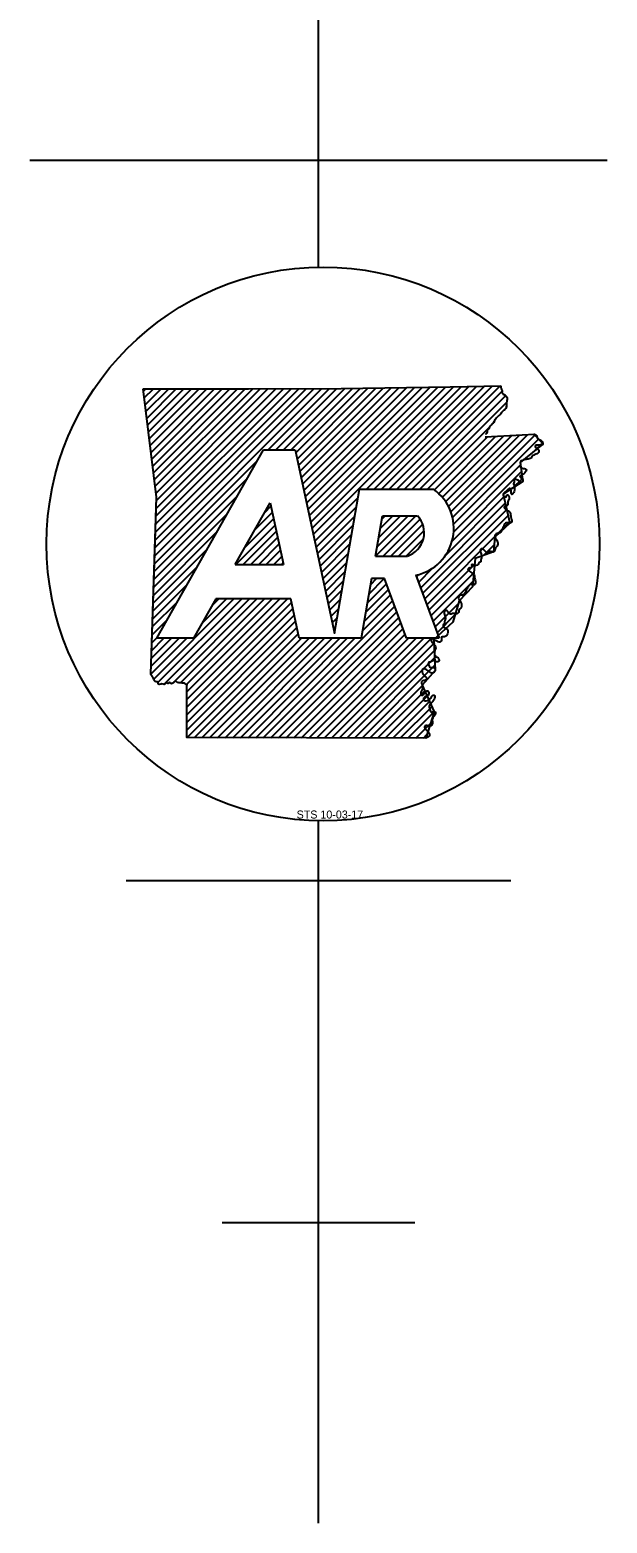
# Model space of a CAD drawing. Extents: x -13171 to 18763, y -8840 to 11152.
# Drawn here: x 1230 to 1756, y -4773 to -3413 of the extents above; entities that cross this region are included whole.
import ezdxf

# ---------------------------------------------------------------- set-up
doc = ezdxf.new("R2010")
doc.units = 0
doc.layers.add('Level 48', color=7, linetype='Continuous')

msp = doc.modelspace()

# ---------------------------------------------------------------- linework, layer by layer
at = {"layer": 'Level 48'}
for p, q in [((1493.4, -3629.5), (1493.4, -2053.7)), ((1230.2, -3532.1), (1756.5, -3532.1)), ((1478.8, -3827.2), (1566.7, -3739.3)), ((1480, -3833), (1573.8, -3739.2)), ((1481.3, -3838.7), (1580.9, -3739.1)), ((1482.5, -3844.4), (1587.9, -3739)), ((1483.7, -3850.2), (1595, -3738.9)), ((1484.9, -3855.9), (1602.1, -3738.8)), ((1486.2, -3861.6), (1609.2, -3738.7)), ((1487.4, -3867.4), (1616.3, -3738.5)), ((1488.6, -3873.1), (1623.4, -3738.4)), ((1537, -3831.7), (1630.5, -3738.2)), ((1544, -3831.7), (1637.7, -3738)), ((1550.9, -3831.7), (1644.8, -3737.9)), ((1557.9, -3831.7), (1651.9, -3737.7)), ((1564.9, -3831.7), (1659, -3737.5)), ((1333.7, -3742.4), (1335.9, -3740.3)), ((1334.5, -3748.6), (1342.9, -3740.3)), ((1335.3, -3754.8), (1349.8, -3740.3)), ((1336, -3761), (1356.8, -3740.3)), ((1336.8, -3767.2), (1363.7, -3740.3)), ((1337.6, -3773.4), (1370.7, -3740.3)), ((1338.4, -3779.6), (1377.7, -3740.3)), ((1339.1, -3785.8), (1384.6, -3740.3)), ((1339.9, -3792), (1391.6, -3740.3)), ((1340.7, -3798.2), (1398.6, -3740.3)), ((1341.4, -3804.4), (1405.5, -3740.3)), ((1342.2, -3810.6), (1412.5, -3740.3)), ((1343, -3816.8), (1419.4, -3740.3)), ((1343.8, -3823), (1426.4, -3740.3)), ((1344, -3892.4), (1496.2, -3740.2)), ((1344.2, -3885.2), (1489.2, -3740.2)), ((1344.5, -3878), (1482.2, -3740.2)), ((1344.5, -3829.1), (1433.4, -3740.3)), ((1344.7, -3870.8), (1475.3, -3740.2)), ((1344.9, -3863.6), (1468.3, -3740.2)), ((1345.2, -3856.4), (1461.3, -3740.2)), ((1345.3, -3835.3), (1440.3, -3740.3)), ((1345.4, -3849.2), (1454.3, -3740.3)), ((1345.7, -3841.9), (1447.3, -3740.3)), ((1447.4, -3795.9), (1503.2, -3740.2)), ((1454.4, -3795.9), (1510.2, -3740.1)), ((1461.4, -3795.9), (1517.2, -3740.1)), ((1468.3, -3795.9), (1524.3, -3740)), ((1472.7, -3798.5), (1531.3, -3739.9)), ((1473.9, -3804.3), (1538.4, -3739.8)), ((1475.1, -3810), (1545.5, -3739.6)), ((1476.3, -3815.7), (1552.6, -3739.5)), ((1477.6, -3821.5), (1559.6, -3739.4)), ((1571.8, -3831.7), (1660.6, -3742.9)), ((1578.8, -3831.7), (1664, -3746.5)), ((1585.8, -3831.7), (1664.9, -3752.6)), ((1592.7, -3831.7), (1649, -3775.5)), ((1599.1, -3832.3), (1647.6, -3783.8)), ((1602.9, -3835.5), (1654.9, -3783.4)), ((1606.3, -3839.1), (1662.3, -3783.1)), ((1609.3, -3843), (1669.6, -3782.7)), ((1611.9, -3847.4), (1677, -3782.3)), ((1614, -3852.2), (1684.3, -3781.9)), ((1615.6, -3857.6), (1690.9, -3782.3)), ((1616.5, -3863.6), (1694.2, -3786)), ((1691.1, -3796), (1697.4, -3789.7)), ((1343.7, -3899.6), (1437.7, -3805.6)), ((1346.1, -3967.5), (1443.2, -3795.9)), ((1443.2, -3795.9), (1472.1, -3795.9)), ((1615.1, -3879), (1678.4, -3815.7)), ((1616.6, -3870.5), (1677.6, -3809.6)), ((1343.5, -3906.8), (1428.6, -3821.6)), ((1530.7, -3831.7), (1598.2, -3831.7)), ((1670.5, -3830.5), (1679.2, -3821.9)), ((1343.3, -3914), (1419.6, -3837.7)), ((1417.5, -3900.2), (1449.3, -3844)), ((1444.4, -3852.8), (1450, -3847.1)), ((1489.9, -3878.9), (1529.4, -3839.3)), ((1491.1, -3884.6), (1527.9, -3847.8)), ((1586.4, -3921.7), (1663.6, -3844.4)), ((1609.1, -3892), (1662.3, -3838.8)), ((1343, -3921.2), (1410.5, -3853.8)), ((1426.2, -3884.9), (1452.4, -3858.6)), ((1435.3, -3868.8), (1451.2, -3852.9)), ((1492.3, -3890.3), (1526.4, -3856.2)), ((1545.4, -3892.6), (1582, -3855.9)), ((1546.8, -3884.2), (1575.1, -3855.9)), ((1548.3, -3875.7), (1568.1, -3855.9)), ((1549.8, -3867.3), (1561.1, -3855.9)), ((1551.2, -3858.9), (1554.2, -3855.9)), ((1551.7, -3855.9), (1583.4, -3855.9)), ((1552.4, -3892.6), (1585.9, -3859)), ((1588.2, -3926.7), (1664.9, -3850.1)), ((1590.1, -3931.8), (1666.2, -3855.8)), ((1592, -3936.9), (1667.5, -3861.4)), ((1342.8, -3928.4), (1401.4, -3869.8)), ((1417.9, -3900.2), (1453.7, -3864.4)), ((1424.8, -3900.2), (1454.9, -3870.1)), ((1493.5, -3896.1), (1525, -3864.6)), ((1494.8, -3901.8), (1523.5, -3873.1)), ((1559.3, -3892.6), (1588.3, -3863.6)), ((1566.3, -3892.6), (1589.6, -3869.3)), ((1342.6, -3935.6), (1392.3, -3885.9)), ((1431.8, -3900.2), (1456.1, -3875.8)), ((1438.8, -3900.2), (1457.4, -3881.6)), ((1445.7, -3900.2), (1458.6, -3887.3)), ((1496, -3907.5), (1522, -3881.5)), ((1573.3, -3892.6), (1589, -3876.9)), ((1643.7, -3892.2), (1653.5, -3882.4)), ((1342.3, -3942.8), (1383.2, -3901.9)), ((1417.5, -3900.2), (1461.3, -3900.2)), ((1452.7, -3900.2), (1459.8, -3893)), ((1459.7, -3900.2), (1461, -3898.8)), ((1497.2, -3913.3), (1520.6, -3889.9)), ((1498.5, -3919), (1519.1, -3898.4)), ((1545.4, -3892.6), (1574.3, -3892.6)), ((1593.9, -3942), (1635.7, -3900.2)), ((1499.7, -3924.8), (1517.6, -3906.8)), ((1500.9, -3930.5), (1516.2, -3915.3)), ((1539.4, -3926.9), (1553.3, -3912.9)), ((1540.9, -3918.4), (1546.3, -3912.9)), ((1553.5, -3912.9), (1541.8, -3912.9)), ((1573.7, -3967.5), (1553.5, -3912.9)), ((1582.1, -3910), (1603.3, -3967.5)), ((1582.6, -3911.5), (1584.7, -3909.4)), ((1584.5, -3916.6), (1597.7, -3903.3)), ((1595.8, -3947.1), (1634.9, -3908)), ((1597.6, -3952.2), (1634.1, -3915.7)), ((1342.1, -3950), (1374.1, -3918)), ((1502.1, -3936.2), (1514.7, -3923.7)), ((1535, -3952.2), (1559.1, -3928)), ((1536.4, -3943.7), (1557.2, -3923)), ((1537.9, -3935.3), (1555.3, -3917.9)), ((1341.8, -3957.2), (1365, -3934.1)), ((1343.1, -4004.7), (1416.3, -3931.5)), ((1347.2, -4007.5), (1423.3, -3931.5)), ((1352.2, -4009.5), (1430.3, -3931.5)), ((1360.5, -4008.2), (1437.2, -3931.5)), ((1367.6, -4008.1), (1444.2, -3931.5)), ((1373.1, -4009.6), (1451.1, -3931.5)), ((1373.3, -4023.3), (1465.1, -3931.5)), ((1373.3, -4016.3), (1458.1, -3931.5)), ((1373.3, -4030.2), (1468.7, -3934.8)), ((1373.3, -4037.2), (1470, -3940.5)), ((1399.8, -3931.5), (1379.4, -3967.5)), ((1387.3, -3953.6), (1409.4, -3931.5)), ((1396.4, -3937.5), (1402.4, -3931.5)), ((1468, -3931.5), (1399.8, -3931.5)), ((1443, -4058), (1562.8, -3938.2)), ((1450, -4058), (1564.7, -3943.3)), ((1503.4, -3942), (1513.2, -3932.1)), ((1504.6, -3947.7), (1511.7, -3940.6)), ((1533.5, -3960.6), (1561, -3933.1)), ((1599.5, -3957.3), (1620.9, -3935.9)), ((1341.6, -3964.4), (1355.9, -3950.1)), ((1373.4, -4044.1), (1471.2, -3946.3)), ((1373.4, -4051.1), (1472.4, -3952)), ((1456.9, -4058), (1566.6, -3948.4)), ((1463.9, -4058.1), (1568.5, -3953.5)), ((1505.8, -3953.5), (1510.3, -3949)), ((1601.4, -3962.4), (1617.9, -3945.9)), ((1340.5, -4000.3), (1373.3, -3967.5)), ((1340.6, -3993.2), (1366.4, -3967.5)), ((1340.9, -3986), (1359.4, -3967.5)), ((1341.1, -3978.8), (1352.4, -3967.5)), ((1341.4, -3971.6), (1346.8, -3966.2)), ((1379.4, -3967.5), (1346.1, -3967.5)), ((1373.5, -4057.9), (1473.7, -3957.7)), ((1380.4, -4057.9), (1474.9, -3963.5)), ((1387.4, -4057.9), (1477.8, -3967.5)), ((1394.4, -4057.9), (1484.8, -3967.5)), ((1401.3, -4058), (1491.8, -3967.5)), ((1408.3, -4058), (1498.7, -3967.5)), ((1415.2, -4058), (1505.7, -3967.5)), ((1422.2, -4058), (1512.7, -3967.5)), ((1429.1, -4058), (1519.6, -3967.5)), ((1436.1, -4058), (1526.6, -3967.5)), ((1470.9, -4058.1), (1570.4, -3958.6)), ((1532.3, -3967.5), (1475.7, -3967.5)), ((1477.8, -4058.1), (1572.2, -3963.7)), ((1484.8, -4058.1), (1575.4, -3967.5)), ((1491.7, -4058.1), (1582.3, -3967.5)), ((1498.7, -4058.1), (1589.3, -3967.5)), ((1505.6, -4058.1), (1596.2, -3967.5)), ((1507, -3959.2), (1508.8, -3957.4)), ((1603.3, -3967.5), (1573.7, -3967.5)), ((1512.6, -4058.1), (1598.6, -3972.1)), ((1519.5, -4058.1), (1598.9, -3978.8)), ((1526.5, -4058.2), (1599.2, -3985.4)), ((1533.4, -4058.2), (1599.5, -3992.1)), ((1540.4, -4058.2), (1588.1, -4010.5)), ((1547.4, -4058.2), (1590.2, -4015.3)), ((1554.3, -4058.2), (1592.4, -4020.1)), ((1561.3, -4058.2), (1594.5, -4025)), ((1568.2, -4058.2), (1596.7, -4029.8)), ((1575.2, -4058.2), (1598.5, -4034.9)), ((1582.1, -4058.3), (1595.3, -4045.1)), ((1589.1, -4058.3), (1592.2, -4055.2)), ((1493.4, -4773.2), (1493.4, -4133.6)), ((1317.9, -4188), (1668.8, -4188)), ((1405.6, -4499.6), (1581.1, -4499.6))]:
    msp.add_line(p, q, dxfattribs=at)
for points in [[(1333.4, -3740.3), (1429.5, -3740.3), (1513.9, -3740.1), (1613.4, -3738.6), (1659.5, -3737.5)], [(1333.5, -3740.3), (1429.6, -3740.3), (1513.9, -3740.1), (1613.4, -3738.6), (1659.5, -3737.5)], [(1344.1, -3889.7), (1345.8, -3839), (1333.4, -3740.3)], [(1340.4, -4000.3), (1345.8, -3839), (1333.5, -3740.3)], [(1689.7, -3781.7), (1698, -3790.4), (1677.3, -3807.4), (1679.5, -3824.6), (1661.7, -3836.3), (1667.8, -3862.8), (1654.1, -3875.3), (1652.9, -3888.9), (1636.2, -3894.9), (1633.6, -3920.5), (1621.6, -3933.4), (1615.9, -3952.7), (1598.4, -3968.6), (1599.7, -3996.8), (1587.9, -4010.1), (1598.7, -4034.3), (1591.2, -4058.3)], [(1645.2, -3783.9), (1690.3, -3781.6)], [(1645.2, -3783.9), (1690.3, -3781.6)], [(1472.1, -3795.9), (1507.8, -3962.9), (1530.7, -3831.7)], [(1449.3, -3844), (1461.3, -3900.2)], [(1545.4, -3892.6), (1551.7, -3855.9)], [(1340.4, -4000.3), (1344.1, -3889.7)], [(1541.8, -3912.9), (1532.3, -3967.5)], [(1475.7, -3967.5), (1468, -3931.5)], [(1591.2, -4058.3), (1373.4, -4057.9), (1373.3, -4009.8)], [(1591.2, -4058.3), (1373.4, -4057.9), (1373.3, -4009.8)]]:
    msp.add_lwpolyline(points, dxfattribs=at)
msp.add_ellipse((1497.5, -3881.6), major_axis=(252.1, 0), ratio=0.999976, dxfattribs=at)
for centre, major_axis, start_param, end_param in [((1573.1, -3867.4), (-43.6, 0), 1.777838, 4.099264), ((1567.4, -3871.4), (-22.3, 0), 1.887169, 3.90762)]:
    msp.add_ellipse(centre, major_axis=major_axis, ratio=0.999987, start_param=start_param, end_param=end_param, dxfattribs=at)
for points in [[(1659.5, -3737.5), (1659.8, -3740.1), (1660.6, -3741.5), (1660.7, -3744), (1661.8, -3745.1), (1663.5, -3746.2), (1665, -3747.8), (1665.4, -3749.9), (1664.9, -3751.9), (1664.8, -3754.3), (1664.6, -3756.3), (1664.2, -3758.1), (1662.8, -3759.6), (1661.4, -3760.7), (1660.2, -3761.9), (1659.3, -3763.3), (1657.7, -3764.7), (1656.2, -3766.2), (1654.9, -3767.5), (1653.7, -3769.1), (1653, -3771), (1651.7, -3772.3), (1650.6, -3773.5), (1649.2, -3775.1), (1648.5, -3776.7), (1647.2, -3778.5), (1646.8, -3780.3), (1646, -3781.7), (1645.9, -3782)], [(1659.5, -3737.5), (1659.8, -3740.1), (1660.6, -3741.5), (1660.7, -3744), (1661.8, -3745.1), (1663.5, -3746.1), (1665, -3747.9), (1665.4, -3749.9), (1664.9, -3752), (1664.8, -3754.3), (1664.5, -3756.3), (1664.2, -3758.1), (1662.8, -3759.6), (1661.4, -3760.7), (1660.1, -3761.9), (1659.3, -3763.3), (1657.7, -3764.7), (1656.2, -3766.2), (1654.9, -3767.5), (1653.7, -3769.1), (1653.1, -3771), (1651.7, -3772.3), (1650.6, -3773.5), (1649.2, -3775.1), (1648.5, -3776.7), (1647.1, -3778.5), (1646.8, -3780.3), (1645.9, -3781.7), (1645.9, -3782)], [(1689.7, -3781.7), (1690.3, -3781.6), (1692.3, -3783.7), (1693.2, -3785.6), (1694.6, -3786.5), (1696.1, -3787.1), (1697.2, -3788.4), (1697.9, -3790), (1697.5, -3791.3), (1695.8, -3791.4), (1694, -3791.7), (1692.2, -3791.6), (1690.8, -3792.8), (1692.1, -3794.4), (1693.8, -3795.9), (1694.3, -3797.5), (1693.4, -3799), (1691.5, -3799.9), (1689.6, -3800.6), (1688, -3802), (1687.2, -3803.4), (1685.3, -3804), (1683.4, -3804.5), (1681.8, -3804.7), (1679.9, -3805.1), (1678.1, -3806), (1677.3, -3807.5), (1677.5, -3809.7), (1677.5, -3812), (1679.4, -3812.7), (1681.1, -3812.8), (1682.8, -3813.7), (1682.6, -3815), (1681.4, -3816.7), (1679.9, -3818), (1678.4, -3818.6), (1677, -3819.9), (1677.5, -3821.2), (1678.7, -3821.9), (1679.6, -3823.3), (1679.5, -3824.6), (1678.1, -3825.5), (1676.5, -3825.1), (1675.4, -3823.6), (1674.1, -3823.2), (1673, -3822.6), (1671.7, -3823.4), (1671.7, -3825.1), (1671.2, -3826.9), (1671.6, -3828.3), (1672.1, -3830.2), (1672.1, -3831.6), (1671.6, -3833.7), (1670.6, -3835.8), (1669.5, -3836.4), (1668.9, -3834.2), (1668.7, -3832.3), (1668, -3831.2), (1667, -3831.2), (1665.8, -3832.1), (1664.4, -3833.5), (1662.7, -3834.9), (1661.7, -3836.4), (1662.2, -3838.2), (1663.5, -3838.7), (1664.6, -3838.4), (1665.1, -3837.2), (1666, -3837), (1667, -3838.9)], [(1667, -3838.9), (1667.3, -3840.6), (1666.3, -3842.4), (1665.9, -3844.2), (1666, -3846.1), (1664.2, -3847.1), (1662.5, -3848.3), (1663.5, -3849.7), (1665.3, -3851), (1667, -3852), (1668.1, -3853.1), (1668.4, -3855.5), (1668.8, -3857), (1669.4, -3859.2), (1669.6, -3860.7), (1668.5, -3862.4), (1667.3, -3862.8), (1665.9, -3862.4), (1664.4, -3862.3), (1663.2, -3863.4), (1662.3, -3865.1), (1661.4, -3866.8), (1660.7, -3868.2), (1660.1, -3869.7), (1658.8, -3871.6), (1657.2, -3871.8), (1655.3, -3872.3), (1654.1, -3873.6), (1654.3, -3875.8), (1655.4, -3877.3), (1656.2, -3879.1), (1656.8, -3880.7), (1656.5, -3882.8), (1655.7, -3884.3), (1654.6, -3885.2), (1654.1, -3887), (1653.4, -3888.5), (1652.7, -3889), (1651.2, -3888.8), (1649.7, -3888.5), (1648.4, -3888.7), (1647.2, -3889.3), (1645.9, -3888.9), (1644.6, -3887.4), (1643.5, -3886.4), (1642.3, -3886), (1641, -3886.6), (1640.9, -3888.6), (1641.5, -3890.6), (1642, -3893.3), (1641.5, -3895), (1641.2, -3897.8)], [(1641.2, -3897.8), (1639.2, -3899.3), (1638.2, -3901), (1632.9, -3900.5), (1633.1, -3902.4), (1631.2, -3903.3), (1629.5, -3904.5), (1630.5, -3906), (1632.3, -3907.3), (1634.1, -3908.3), (1635.2, -3909.3), (1635.5, -3911.8), (1635.8, -3913.3), (1636.4, -3915.5), (1636.6, -3916.9), (1635.5, -3918.7), (1634.3, -3919), (1633, -3918.6), (1631.5, -3918.5), (1630.2, -3919.7), (1629.3, -3921.4), (1628.4, -3923), (1627.8, -3924.5), (1627.1, -3926), (1625.8, -3927.8), (1624.2, -3928.1), (1622.3, -3928.5), (1621.2, -3929.8), (1621.4, -3932.1), (1622.4, -3933.5), (1623.3, -3935.4), (1623.8, -3937), (1623.6, -3939), (1622.7, -3940.5), (1621.7, -3941.4), (1621.2, -3943.3), (1620.4, -3944.7), (1619.7, -3945.2), (1618.3, -3945), (1616.7, -3944.8), (1615.4, -3944.9), (1614.2, -3945.5), (1612.9, -3945.1), (1611.6, -3943.7), (1610.5, -3942.6), (1609.3, -3942.2), (1608.1, -3942.9), (1607.9, -3944.8), (1608.5, -3946.8), (1609, -3949.6), (1608.5, -3951.2), (1608.3, -3954)], [(1608.3, -3954), (1608.1, -3954.1), (1607.1, -3955.4), (1607.7, -3957.5), (1610, -3958.4), (1611.1, -3960.4), (1611.1, -3962.1), (1610.4, -3964.6), (1609.3, -3965.7), (1607.2, -3966.2), (1605.6, -3966.5), (1605.4, -3969.2), (1604.6, -3970.6), (1603.4, -3971), (1601.6, -3970.1), (1600.5, -3969.7), (1599.2, -3969.1), (1597.6, -3968.1), (1596.3, -3968.3), (1596.7, -3970.9), (1596.8, -3971), (1598.2, -3973), (1599.6, -3974.5), (1600.3, -3976.4)], [(1608.3, -3954), (1608.1, -3954.1), (1607.1, -3955.4), (1607.7, -3957.5), (1610, -3958.4), (1611.1, -3960.4), (1611.1, -3962.1), (1610.4, -3964.6), (1609.3, -3965.7), (1607.2, -3966.2), (1605.6, -3966.5), (1605.4, -3969.2), (1604.6, -3970.6), (1603.4, -3971), (1601.6, -3970.1), (1600.5, -3969.7), (1599.2, -3969.1), (1597.6, -3968.1), (1596.3, -3968.3), (1596.7, -3970.9), (1596.8, -3971), (1598.2, -3973), (1599.6, -3974.5), (1600.3, -3976.4)], [(1600.3, -3976.4), (1599.7, -3977.8), (1599, -3980.1), (1599.2, -3982.1), (1600.1, -3983.8), (1601.5, -3984.8), (1603.1, -3986.2), (1603, -3988.3), (1602.1, -3989), (1600, -3988.5), (1598.4, -3987.8), (1597, -3988.2), (1595.2, -3989.1), (1593.8, -3989.3), (1593.9, -3992.1), (1595.7, -3994.1), (1597.3, -3994.1), (1599.2, -3994.4), (1599.8, -3996.5), (1598.7, -3998.3), (1597, -3999.2), (1594.7, -3998.1), (1593.1, -3997), (1591.5, -3995.9), (1589.5, -3995.4), (1588.3, -3995.6), (1587.8, -3998.1), (1588.8, -4000.4), (1590.3, -4001.9), (1591.7, -4003.9), (1591.5, -4005.5), (1590.4, -4005.8), (1588.5, -4006.3), (1587.4, -4006.8), (1587.1, -4007.3), (1587.7, -4009.4), (1588.2, -4011.5), (1588.2, -4013.2), (1587.6, -4014.7), (1586.6, -4017.1), (1586.7, -4018.6), (1587.4, -4019.4), (1588.3, -4019.2), (1589.5, -4018.3), (1590.3, -4017.4), (1590.9, -4016.2), (1592.1, -4015.2), (1593.7, -4016.1), (1594, -4017.9), (1593.2, -4019.5), (1591.9, -4020.3), (1590.4, -4020.8), (1589.2, -4022.1), (1589.5, -4023.7), (1590.4, -4024.5), (1592.7, -4024.1), (1594.1, -4023.4), (1595, -4022.6), (1596, -4021.6), (1596.5, -4020.6), (1597.3, -4019.5), (1598.7, -4019.2), (1599.3, -4020.1), (1599, -4022.1), (1598.2, -4024.1), (1597.1, -4025.6), (1595.8, -4026.7), (1594.3, -4029.2), (1594.6, -4031.4), (1595.2, -4033.3), (1596, -4034.7), (1597.4, -4034.4), (1599, -4034.3), (1600, -4035), (1599.9, -4036.7), (1598.7, -4038.3), (1597.6, -4039.9), (1597, -4042), (1597.2, -4043.5), (1597.2, -4044.8), (1596.7, -4046.3), (1595.9, -4047.2), (1593.7, -4047.1), (1591.4, -4046.9), (1590.2, -4047.6), (1590.4, -4049.6), (1591.7, -4051.1), (1592.7, -4051.8), (1594, -4053.5), (1594.6, -4054.9), (1594.5, -4056.1), (1593.6, -4057.1), (1591.2, -4058.3)], [(1600.3, -3976.4), (1599.7, -3977.8), (1599, -3980.1), (1599.2, -3982.1), (1600.1, -3983.8), (1601.5, -3984.8), (1603.1, -3986.2), (1603, -3988.3), (1602.1, -3989), (1600, -3988.5), (1598.4, -3987.8), (1597, -3988.2), (1595.2, -3989.1), (1593.8, -3989.3), (1593.9, -3992.1), (1595.7, -3994.1), (1597.3, -3994.1), (1599.2, -3994.4), (1599.8, -3996.5), (1598.7, -3998.3), (1597, -3999.2), (1594.7, -3998.1), (1593.1, -3997), (1591.5, -3995.9), (1589.5, -3995.4), (1588.3, -3995.6), (1587.8, -3998.1), (1588.8, -4000.4), (1590.3, -4001.9), (1591.7, -4003.9), (1591.5, -4005.5), (1590.4, -4005.8), (1588.5, -4006.3), (1587.4, -4006.8), (1587.1, -4007.3), (1587.7, -4009.4), (1588.2, -4011.5), (1588.2, -4013.2), (1587.6, -4014.7), (1586.6, -4017.1), (1586.7, -4018.6), (1587.4, -4019.4), (1588.3, -4019.2), (1589.5, -4018.3), (1590.3, -4017.4), (1590.9, -4016.2), (1592.1, -4015.2), (1593.7, -4016.1), (1594, -4017.9), (1593.2, -4019.5), (1591.9, -4020.3), (1590.4, -4020.8), (1589.2, -4022.1), (1589.5, -4023.7), (1590.4, -4024.5), (1592.7, -4024.1), (1594.1, -4023.4), (1595, -4022.6), (1596, -4021.6), (1596.5, -4020.6), (1597.3, -4019.5), (1598.7, -4019.2), (1599.3, -4020.1), (1599, -4022.1), (1598.2, -4024.1), (1597.1, -4025.6), (1595.8, -4026.7), (1594.3, -4029.2), (1594.6, -4031.4), (1595.2, -4033.3), (1596, -4034.7), (1597.4, -4034.4), (1599, -4034.3), (1600, -4035), (1599.9, -4036.7), (1598.7, -4038.3), (1597.6, -4039.9), (1597, -4042), (1597.2, -4043.5), (1597.2, -4044.8), (1596.7, -4046.3), (1595.9, -4047.2), (1593.7, -4047.1), (1591.4, -4046.9), (1590.2, -4047.6), (1590.4, -4049.6), (1591.7, -4051.1), (1592.7, -4051.8), (1594, -4053.5), (1594.6, -4054.9), (1594.5, -4056.1), (1593.6, -4057.1), (1591.2, -4058.3)], [(1373.3, -4009.8), (1373.5, -4009.9), (1372.4, -4009.2), (1370.8, -4008.4), (1369.1, -4008.3), (1366.9, -4008), (1365.1, -4007.8), (1363.2, -4006.6), (1361.2, -4007.8), (1358.9, -4008.8), (1357.6, -4007.7), (1355.9, -4008.5), (1354.7, -4008.1), (1352.6, -4009.5), (1350.6, -4009), (1349.2, -4009.4), (1347.4, -4009.4), (1347.1, -4007.3), (1345.3, -4007.1), (1343.8, -4006.2), (1342.9, -4004.1), (1342.1, -4002.5), (1340.4, -4000.3)], [(1373.3, -4009.8), (1373.5, -4010), (1372.4, -4009.2), (1370.8, -4008.4), (1369.1, -4008.3), (1366.9, -4008), (1365.1, -4007.8), (1363.2, -4006.6), (1361.2, -4007.9), (1358.9, -4008.8), (1357.6, -4007.8), (1355.9, -4008.5), (1354.7, -4008.1), (1352.6, -4009.5), (1350.6, -4009), (1349.2, -4009.4), (1347.4, -4009.4), (1347.1, -4007.3), (1345.3, -4007), (1343.9, -4006.2), (1342.8, -4004.1), (1342.1, -4002.5), (1340.4, -4000.3)]]:
    msp.add_spline(points, degree=3, dxfattribs=at)

# ---------------------------------------------------------------- texts
msp.add_text('STS 10-03-17', height=7.288, dxfattribs=at).set_placement((1473.4, -4131.6))

doc.saveas('drawing.dxf')
